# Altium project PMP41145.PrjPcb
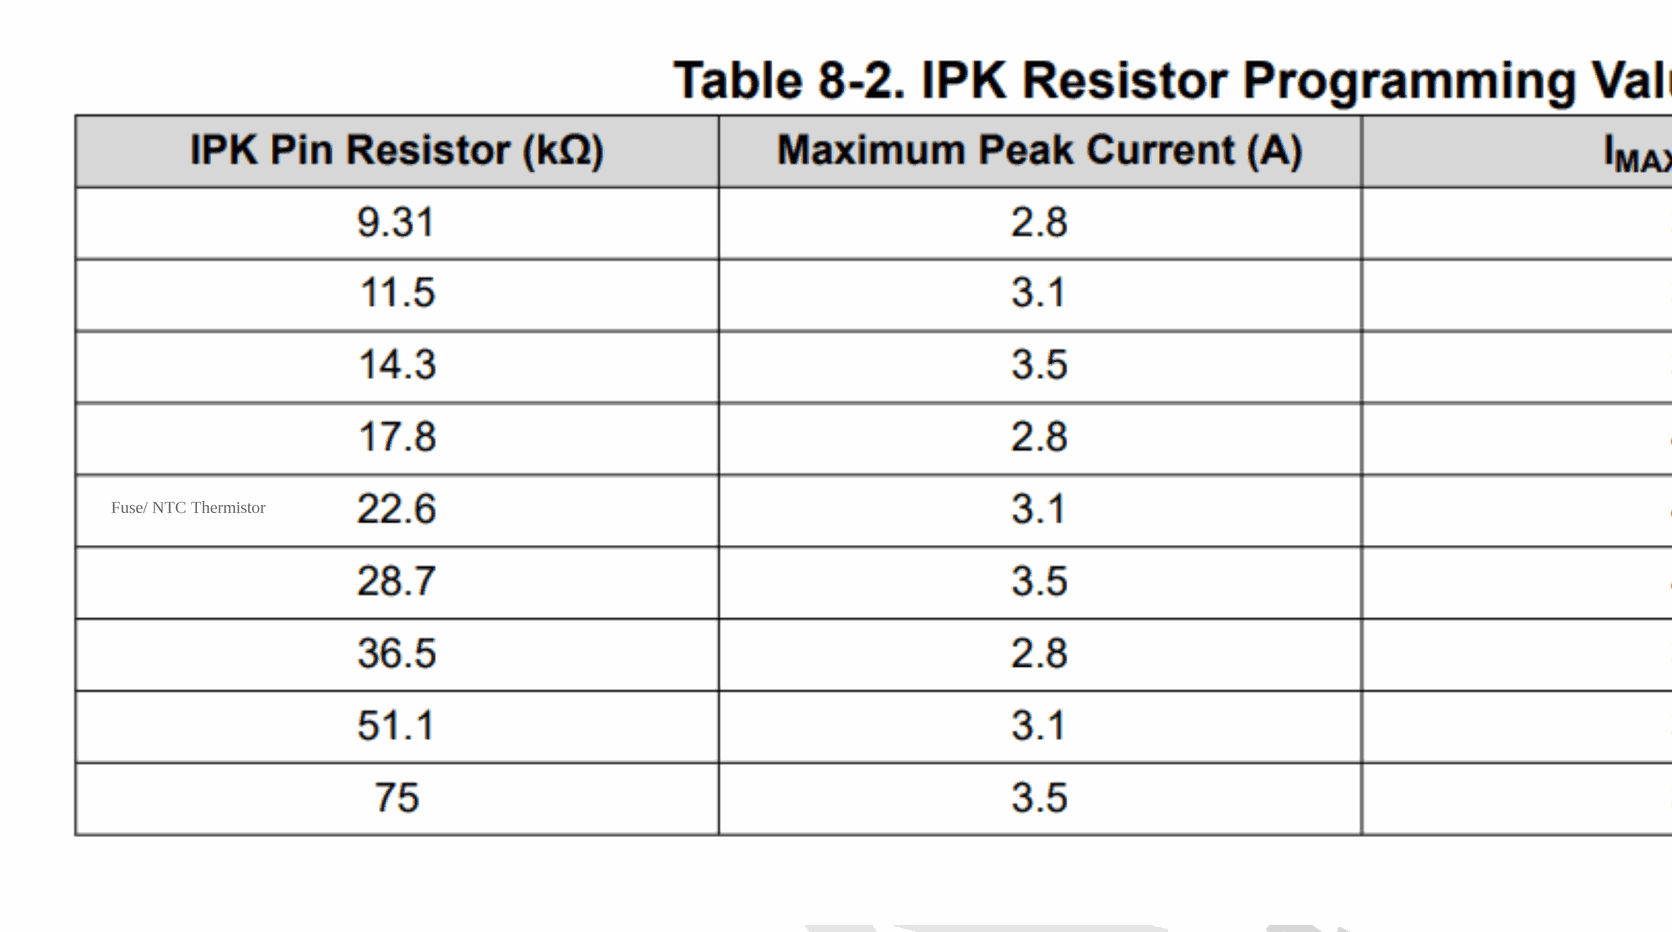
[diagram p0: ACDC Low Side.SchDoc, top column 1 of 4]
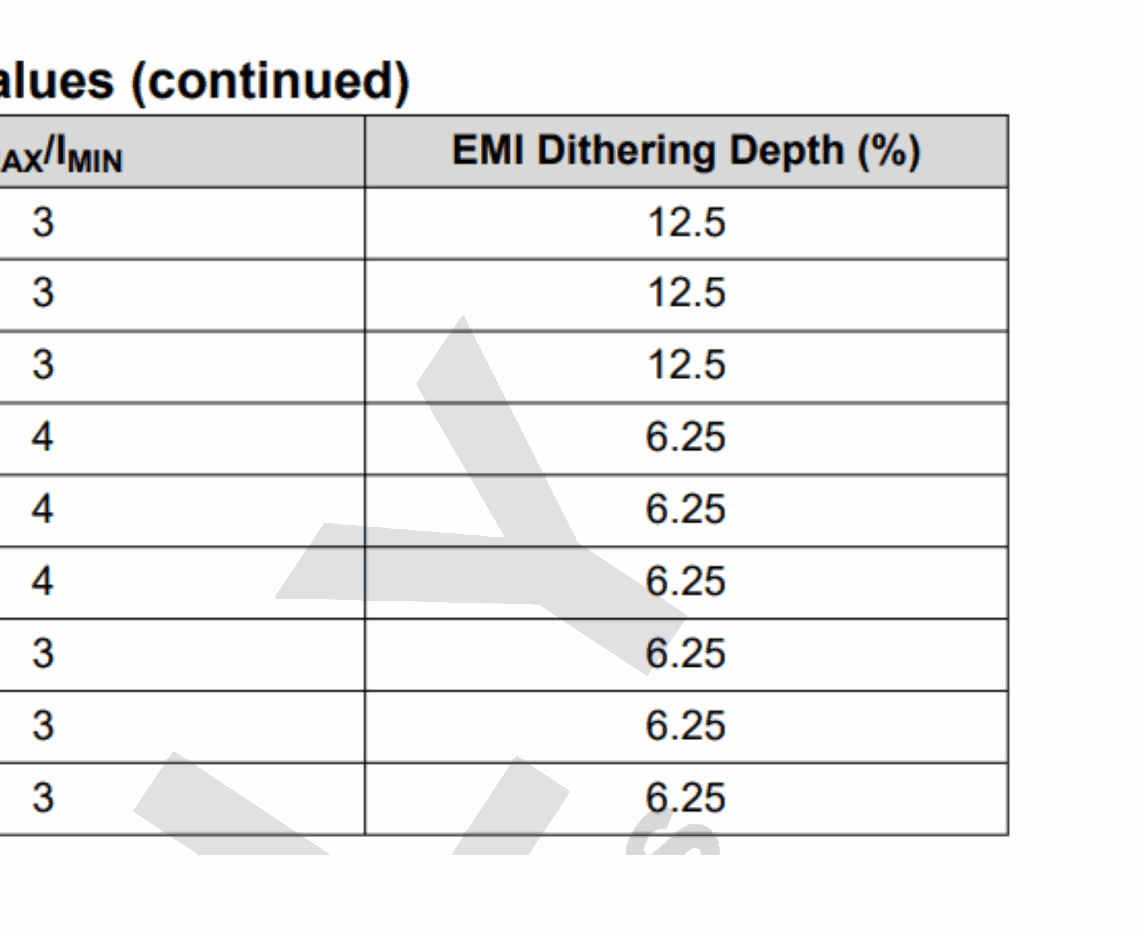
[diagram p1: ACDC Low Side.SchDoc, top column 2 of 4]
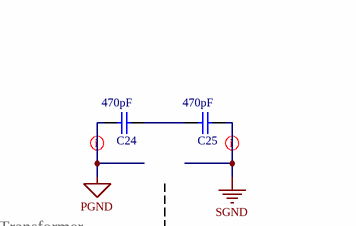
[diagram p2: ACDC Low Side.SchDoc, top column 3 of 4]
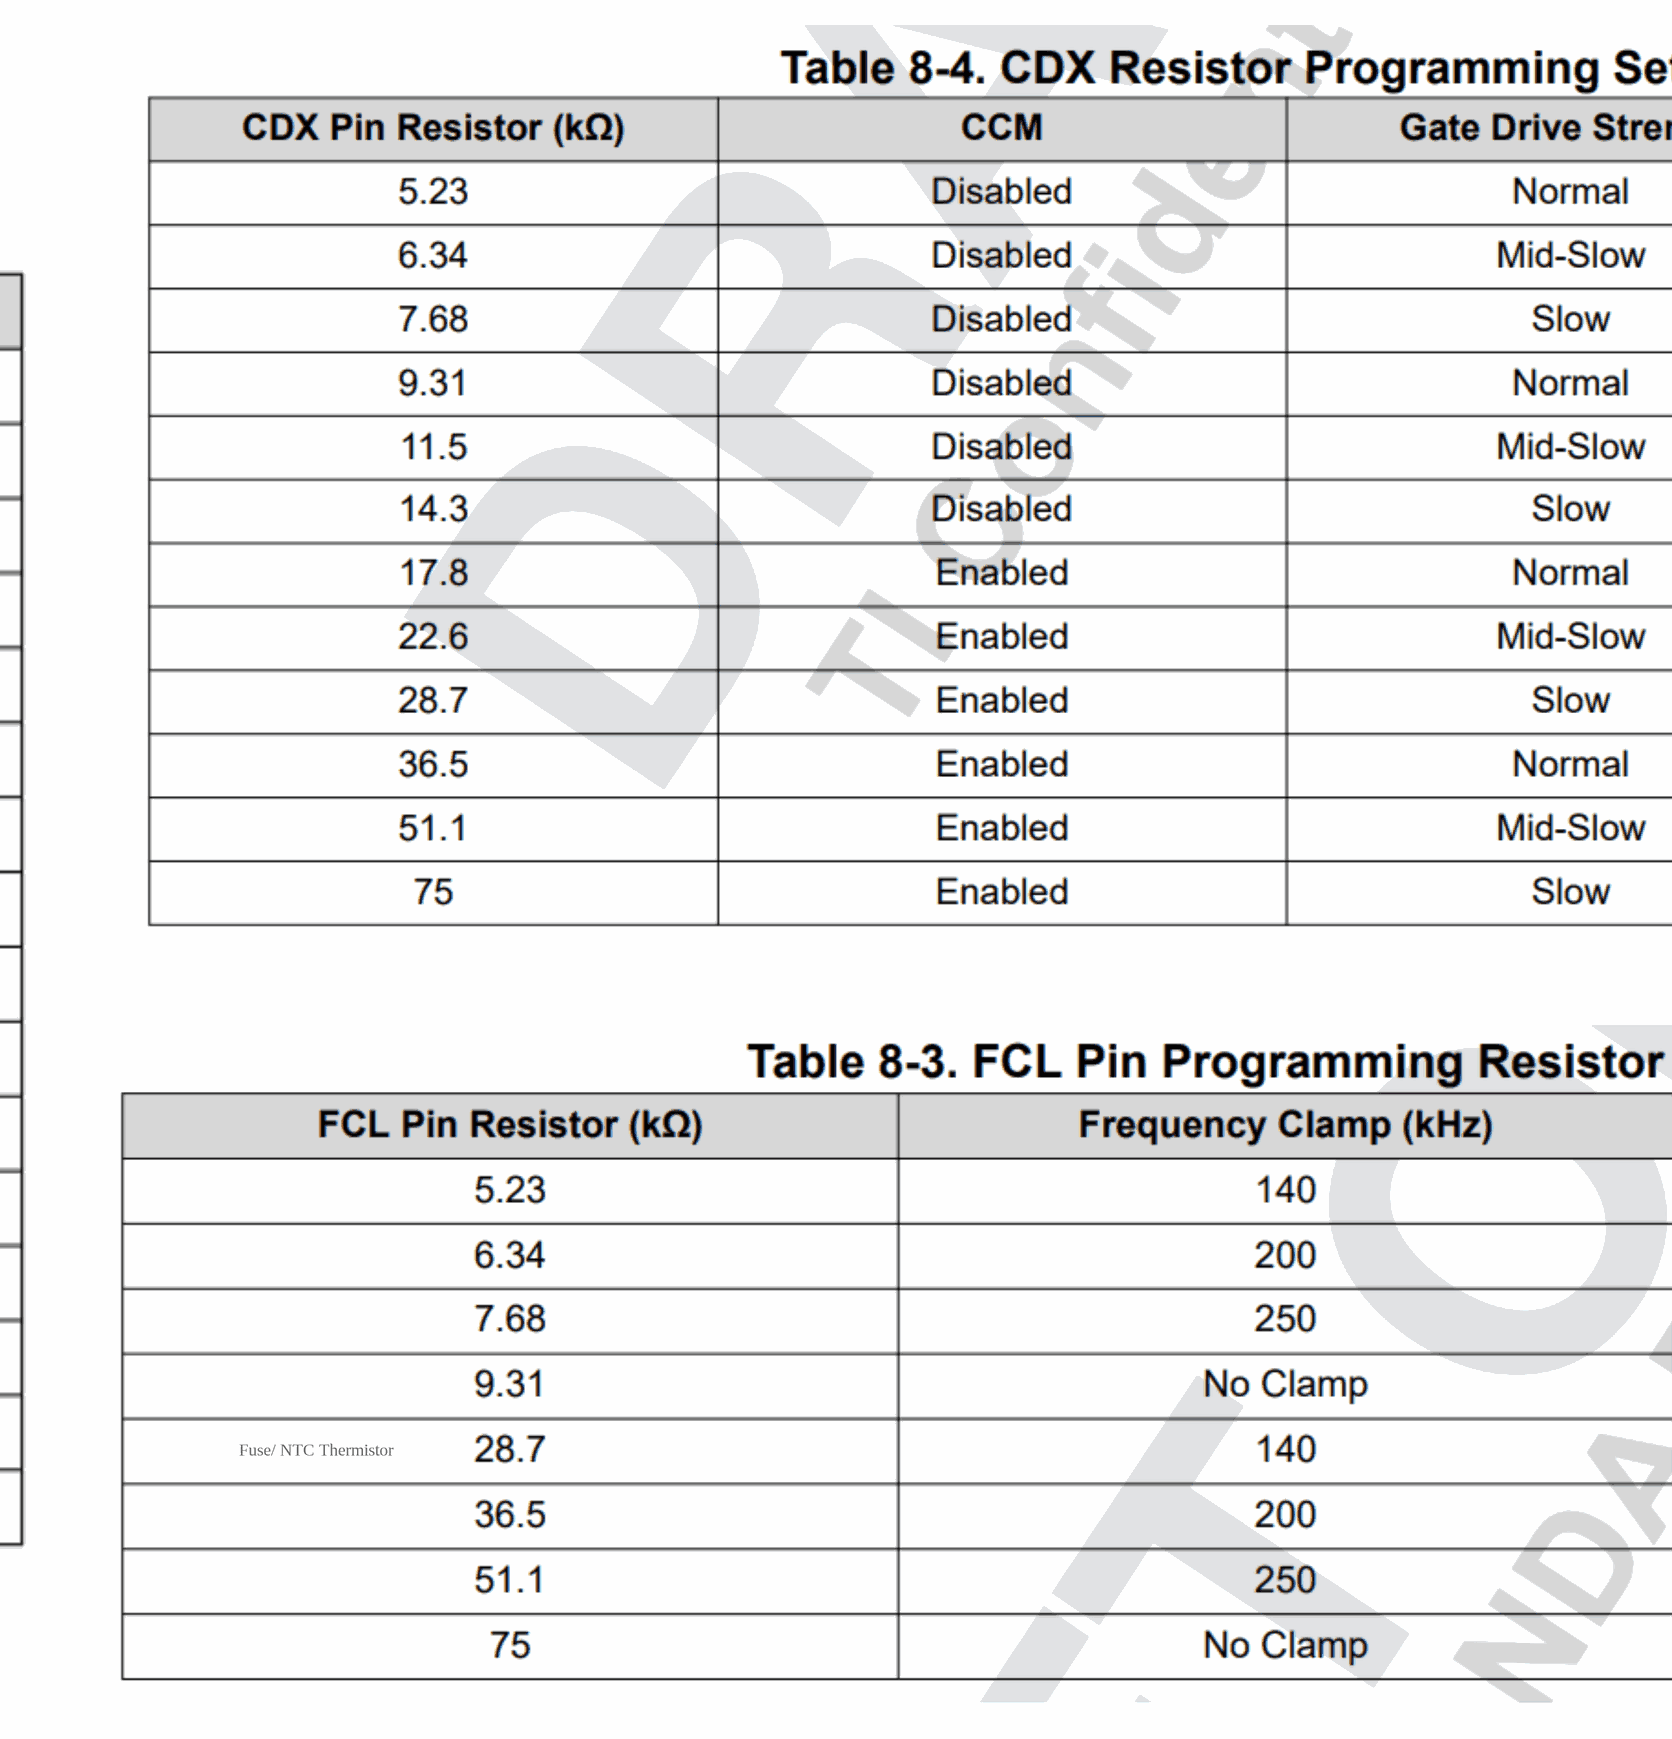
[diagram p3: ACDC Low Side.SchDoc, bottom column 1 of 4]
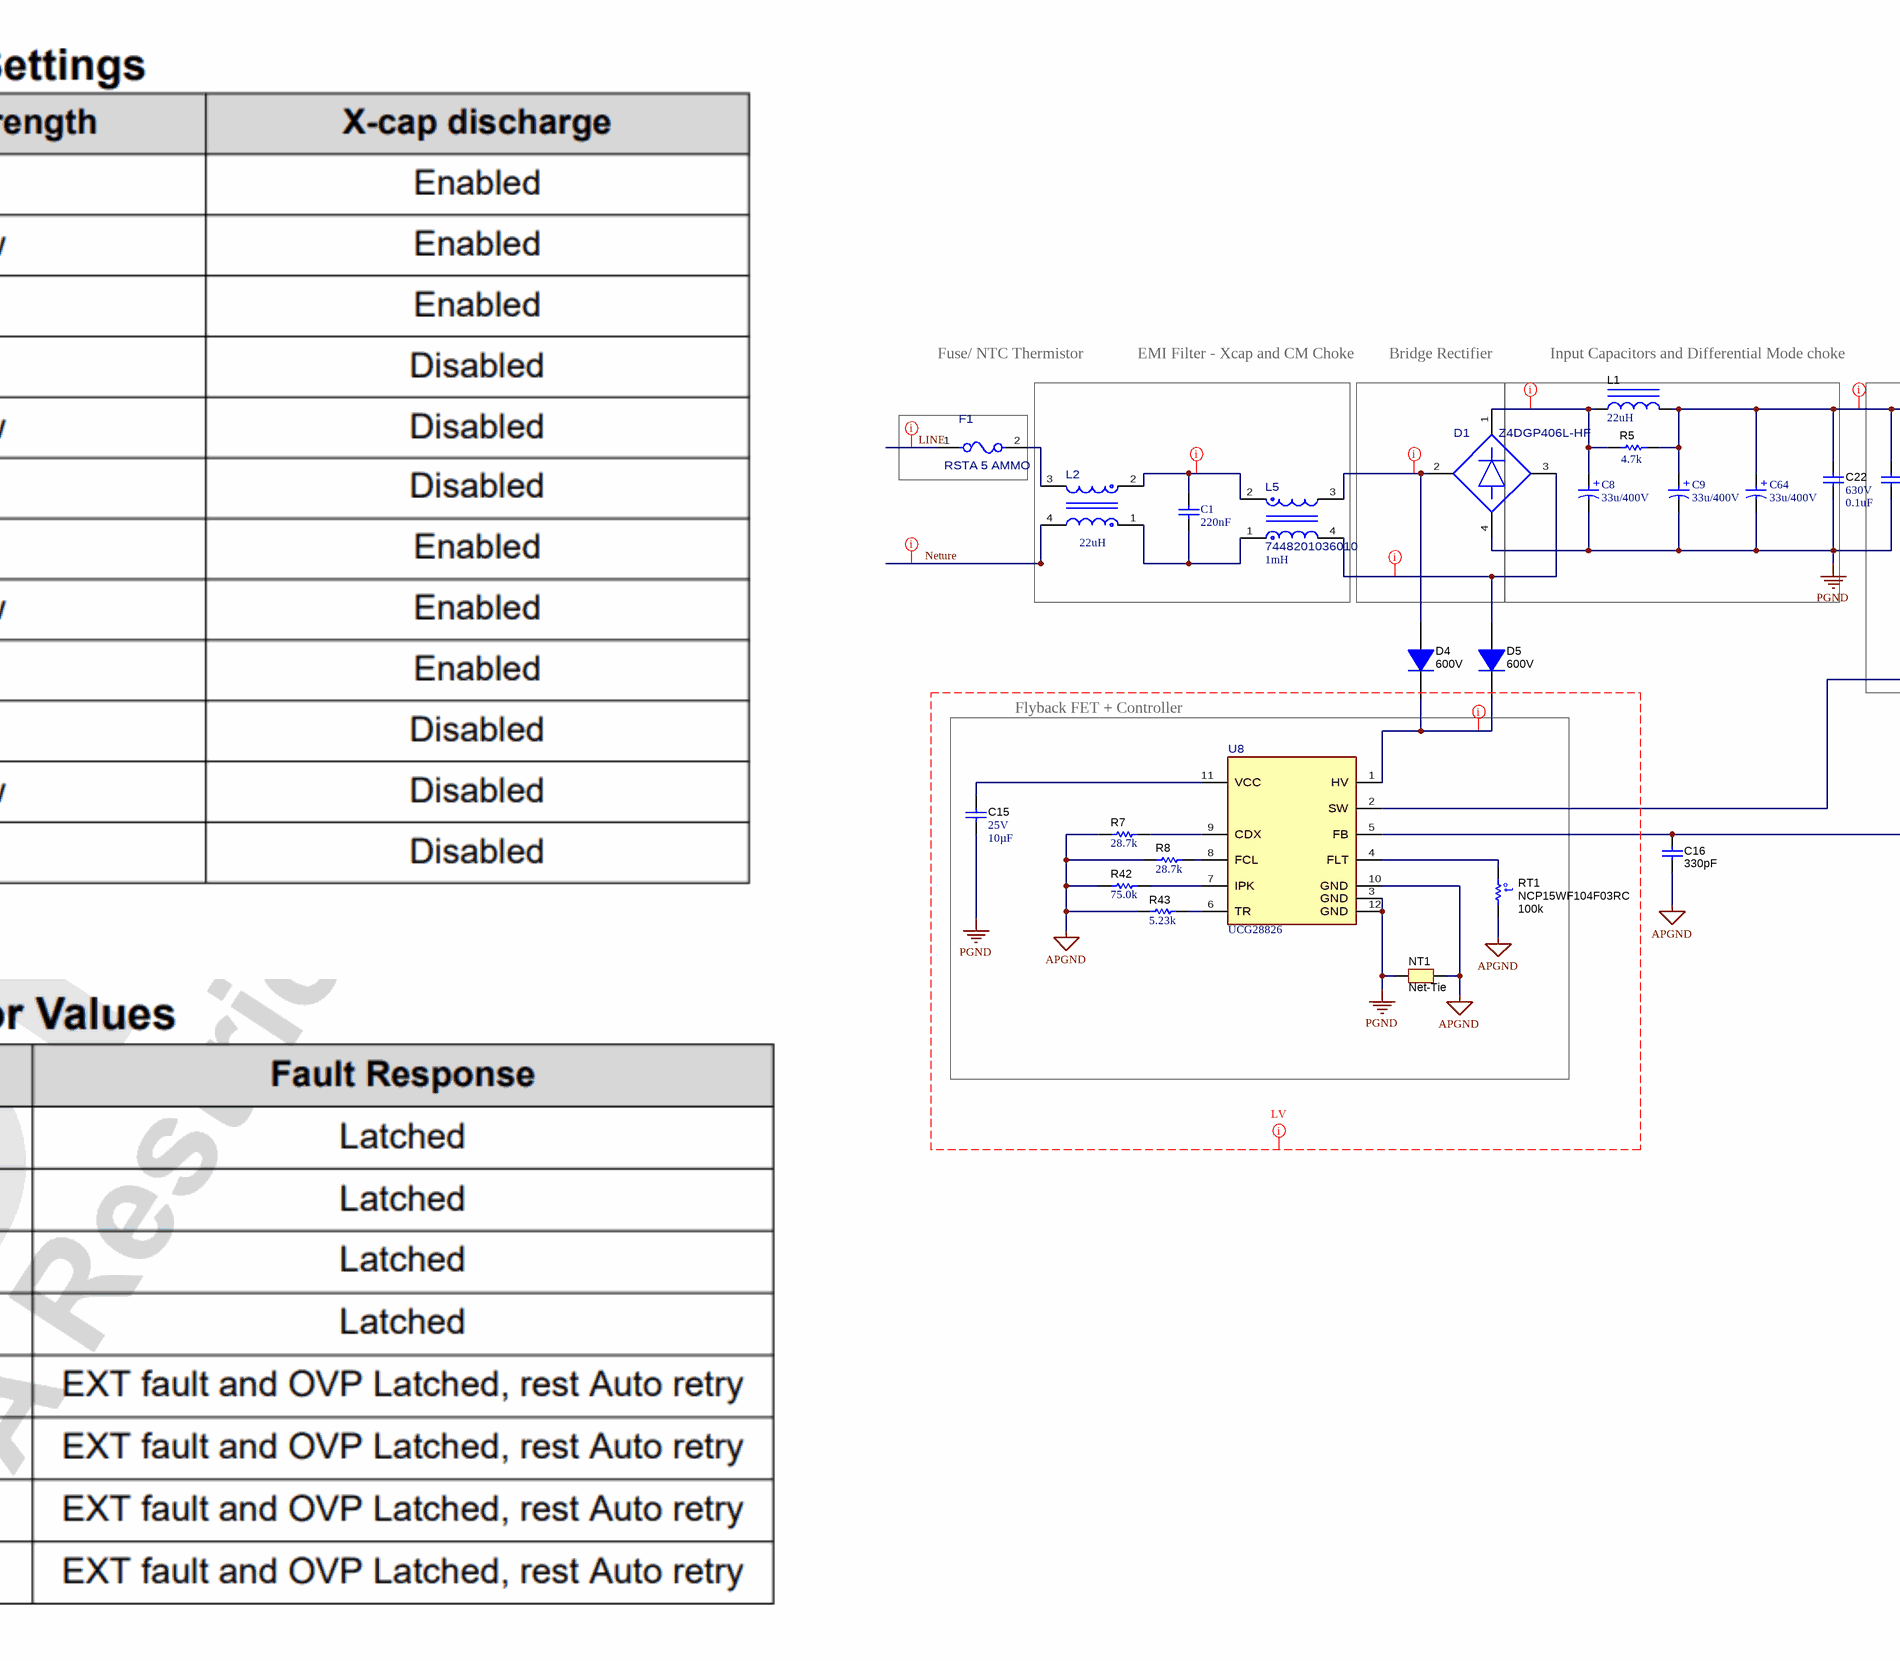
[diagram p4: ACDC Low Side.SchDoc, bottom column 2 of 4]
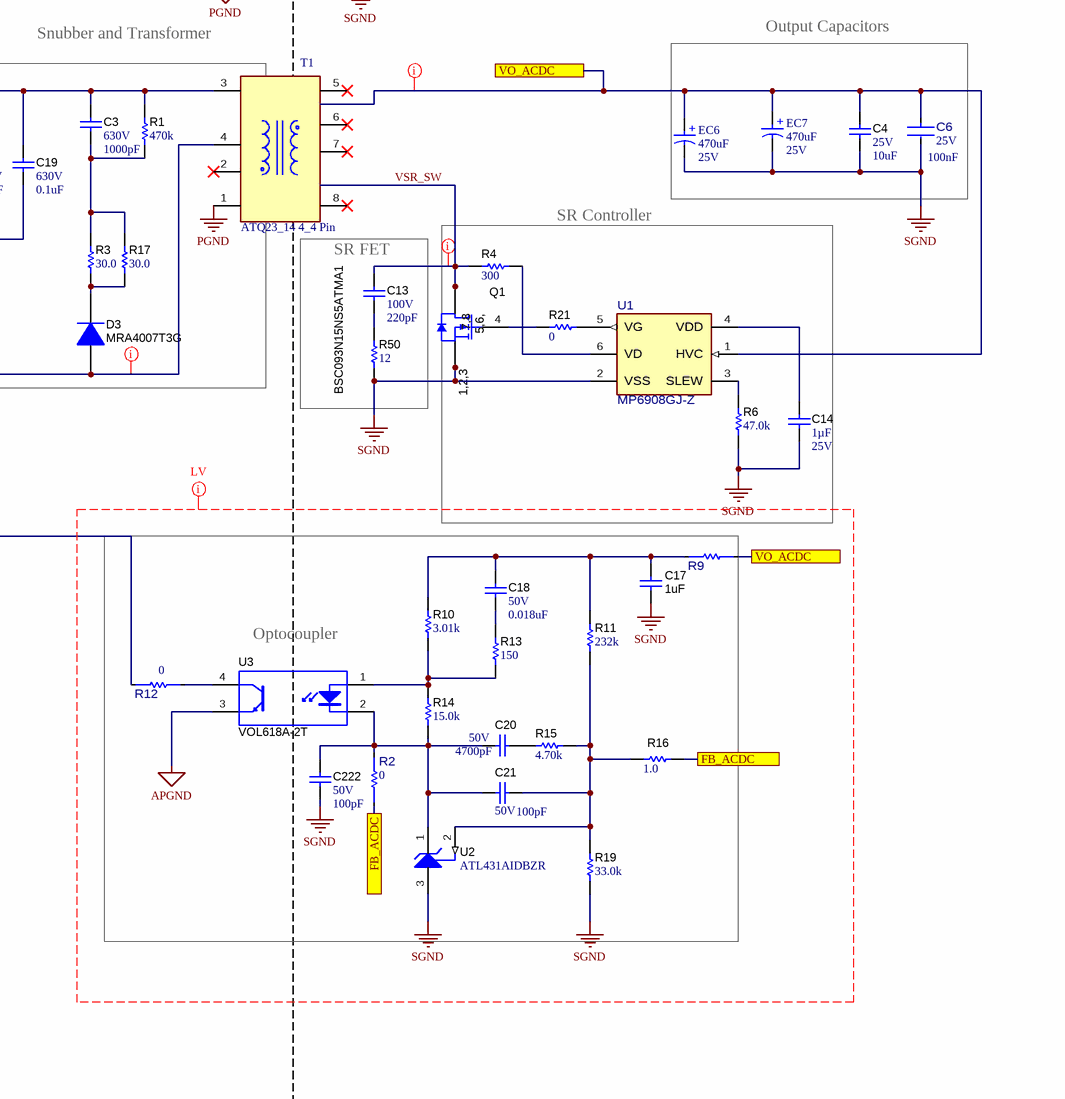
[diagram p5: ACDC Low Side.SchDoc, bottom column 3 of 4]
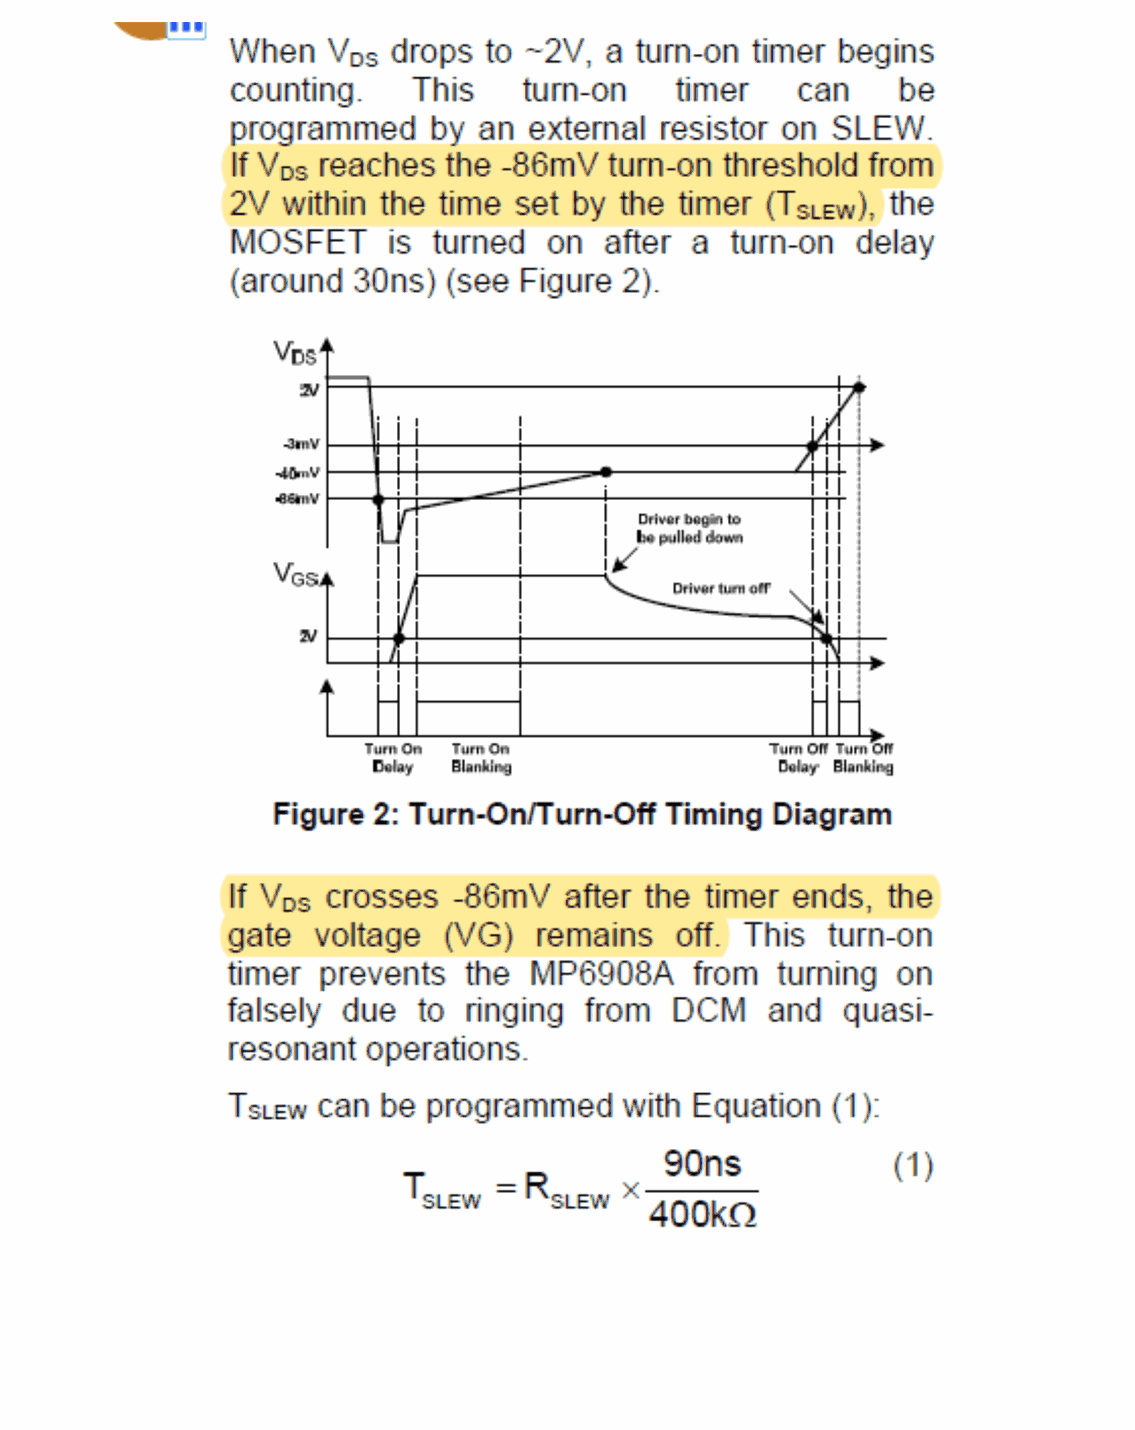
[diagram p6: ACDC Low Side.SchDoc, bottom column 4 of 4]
CopyrightYear: 2018; PCB_Layout: Max Wang; PCB_Rev: E1; PRJ_Customer: Public Release; PRJ_Engineer: Max Wang; PRJ_Number: PMP411145; PRJ_Title: Change in menu Project|Project Options|Parameters; SCH_Rev: E1; TechSupport: http://www.ti.com/support; TID: N/A
1 sheet, 60 parts. Net scope: flat (ports and power ports of the same name join across sheets).
Board file: PMP41145 ACDC.PcbDoc

## Sheet ACDC Low Side.SchDoc
size 431 x 279 mm; Date: Not shown in title block; ApprovedBy: Not shown in title block; CheckedBy: Not shown in title block; Author: Not shown in title block; CompanyName: Not shown in title block; Engineer: Not shown in title block; Organization: Not shown in title block; Address1: Not shown in title block; Address2: Not shown in title block; Address3: Not shown in title block; Address4: Not shown in title block; DocumentNumber: 1; Revision: Use project parameter SCH_Rev; SheetNumber: 1; SheetTotal: 1; PageSetup: Record=PageOptions¦CenterHorizontal=True¦CenterVertical=True¦PrintScale=1.00¦XCorrection=1.00¦YCorrection=1.00¦PrintKind=0¦BorderSize=5000000¦LeftOffset=0¦BottomOffset=0¦Orientation=2¦PaperLength=1000¦PaperWidth=1000¦Scale=100¦PaperSource=15¦PrintQuality=600¦MediaType=1¦DitherType=10¦PaperKind=Letter¦PrintScaleMode=1

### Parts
C1  value 220nF  [X CAP small form 7_10_8]  (hidden comment: 890324023028)
C3  VDC_V: 630V  ValueDisplayed: 1000pF  [1206]  (hidden comment: GRM31BR72J102KW01L)
C4  VDC_V: 25V  ValueDisplayed: 10uF  [0805_HV]  (hidden comment: TMK212BBJ106KG-T)
C6  VDC_V: 25V  Cap_F: 100nF  [FP-CGA3E2X8R1E104K080AD_0603-MFG]  (hidden comment: CGA3E2X8R1E104K080AD)
C8  33u/400V  [WCAP-ATG5_D8H16]
C9  33u/400V  [WCAP-ATG5_D8H16]
C13  VDC_V: 100V  ValueDisplayed: 220pF  [0603]  (hidden comment: GRM1885C2A221JA01D)
C14  Cap_F: 1µF  VDC_V: 25V  [0603S]  (hidden comment: CGA3E1X7R1E105K080AC)
C15  VDC_V: 25V  ValueDisplayed: 10µF  [0603]  (hidden comment: GRM188R61E106KA73D)
C16  ValueDisplayed: 330pF  [0402S]  (hidden comment: GRM155R71H331KA01D)
C17  ValueDisplayed: 1uF  [0603S]  (hidden comment: C1608X7R1E105K080AB)
C18  VDC_V: 50V  ValueDisplayed: 0.018uF  [0402]  (hidden comment: GRM155R71H183KA12D)
C19  VDC_V: 630V  ValueDisplayed: 0.1uF  [1206_180]  (hidden comment: C3216X7T2W104M160AA)
C20  VDC_V: 50V  ValueDisplayed: 4700pF  [0402]  (hidden comment: GRM155R71H472KA01D)
C21  VDC_V: 50V  ValueDisplayed: 100pF  [0402S]  (hidden comment: 885012205055)
C22  VDC_V: 630V  ValueDisplayed: 0.1uF  [1206_180]  (hidden comment: C3216X7T2W104M160AA)
C24  Cap_F: 470pF  [WCAP-CSSA_1808_L4.5W2H1.6]  (hidden comment: 885362210009)
C25  Cap_F: 470pF  [WCAP-CSSA_1808_L4.5W2H1.6]  (hidden comment: 885362210009)
C64  33u/400V  [WCAP-ATG5_D8H16]
C222  VDC_V: 50V  ValueDisplayed: 100pF  [0402S]  (hidden comment: 885012205055)
D1  Z4DGP406L-HF  [FP-Z4DGP406L-HF_SMT_8MM1_10MM5-MFG]
D3  MRA4007T3G  [SMA]
D4  value 600V  [SOD-123]  (hidden comment: ES1JFL)
D5  value 600V  [SOD-123]  (hidden comment: ES1JFL)
EC6  value 470uF  Voltage: 25V  [CE05.5P254L11]  (hidden comment: ECAP_LAYDOWN)
EC7  value 470uF  Voltage: 25V  [CE05.5P254L11]  (hidden comment: ECAP_LAYDOWN)
F1  RSTA 5 AMMO  [FUSE]
L1  ValueDisplayed: 22uH  [WE-TI_5075]  (hidden comment: 7447462220)
L2  value 22uH  [L-T8*5]  (hidden comment: CMP-0088773-1)
L5  7448201036010  value 1mH  [CM Choke_Small]
NT1  Net-Tie  [Net-Tie_10milWide_30milLong]  (net tie, no BOM)
Q1  BSC093N15NS5ATMA1  [PG-TDSON-8]
R1  ValueDisplayed: 470k  [0805_HV]  (hidden comment: CRCW0805470KJNEA)
R2  Res_ohm: 0  [FP-CRCW04020000Z0EDHP_0402-MFG]  (hidden comment: CRCW04020000Z0EDHP)
R3  ValueDisplayed: 30.0  [1206]  (hidden comment: RC1206FR-0730RL)
R4  ValueDisplayed: 300  [0603]  (hidden comment: RC0603FR-07300RL)
R5  ValueDisplayed: 4.7k  [1206]  (hidden comment: CRCW12064K70JNEA)
R6  ValueDisplayed: 47.0k  [0603]  (hidden comment: CRCW060347K0FKEA)
R7  ValueDisplayed: 28.7k  [0402]  (hidden comment: CRCW040228K7FKED)
R8  ValueDisplayed: 28.7k  [0402]  (hidden comment: CRCW040228K7FKED)
R9  CRCW04020000Z0EDHP  [FP-CRCW04020000Z0EDHP_0402-MFG]  (value not drawn)
R10  ValueDisplayed: 3.01k  [0402]  (hidden comment: CRCW04023K01FKED)
R11  ValueDisplayed: 232k  [0603]  (hidden comment: RC0603FR-07232KL)
R12  Res_ohm: 0  [FP-CRCW04020000Z0EDHP_0402-MFG]  (hidden comment: CRCW04020000Z0EDHP)
R13  ValueDisplayed: 150  [0402]  (hidden comment: CRCW0402150RFKED)
R14  ValueDisplayed: 15.0k  [0402]  (hidden comment: CRCW040215K0FKED)
R15  ValueDisplayed: 4.70k  [0402]  (hidden comment: RC0402FR-074K7L)
R16  ValueDisplayed: 1.0  [0402]  (hidden comment: CRCW04021R00JNED)
R17  ValueDisplayed: 30.0  [1206]  (hidden comment: RC1206FR-0730RL)
R19  ValueDisplayed: 33.0k  [0603]  (hidden comment: CRCW060333K0FKEA)
R21  ValueDisplayed: 0  [0201]  (hidden comment: CRCW02010000Z0ED)
R42  ValueDisplayed: 75.0k  [0402S]  (hidden comment: CRCW040275K0FKED)
R43  ValueDisplayed: 5.23k  [0402]  (hidden comment: CRCW04025K23FKED)
R50  ValueDisplayed: 12  [0603]  (hidden comment: CRCW060312R0JNEA)
RT1  NCP15WF104F03RC  value 100k  [0402S]
T1  ATQ23_14 4_4 Pin  [ATQ23.9_13.8_Remove Flywire]
U1  MP6908GJ-Z  [FP-MP6908GJ-Z_TSOT23-6-MFG]
U2  ATL431AIDBZR  [DBZ0003A_N]
U3  VOL618A-2T  [SOP254P1020X230-4]
U8  UCG28826  [REZ0012A-MFG]

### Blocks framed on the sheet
Output Capacitors: C4 C6 EC6 EC7
SR Controller: C14 Q1 R4 R6 R21 U1
SR FET: C13 R50
Flyback FET + Controller: C15 NT1 R7 R8 R42 R43 RT1 U8
Optocoupler: C17 C18 C20 C21 C222 R2 R9-R16 R19 U2 U3

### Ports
FB_ACDC, VO_ACDC

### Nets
APGND: C16.2 NT1.2 R7.1 R8.1 R42.1 R43.1 RT1.1 U3.3(E) U8.10(GND)
PGND: C8.2(N) C9.2(N) C15.2 C19.2 C22.2 C24.1 C64.2(N) D1.4(-) NT1.1 T1.1 U8.3(GND) U8.12(GND)
SGND: C4.2 C6.2 C14.2 C17.1 C25.2 C222.1 EC6.2(N) EC7.2(N) Q1.1(S) Q1.2(S) Q1.3(S) R6.1 R19.1 R50.1 U1.2(VSS) U2.3(ANODE)
FB_ACDC: R2.1 R16.2 ; port FB_ACDC
LINE: F1.1
Neture: L2.4
VO_ACDC: C4.1 C6.1 EC6.1(P) EC7.1(P) R9.2 U1.1(HVC) ; port VO_ACDC
VSR_SW: C13.1 Q1.5(D) Q1.6(D) Q1.7(D) Q1.8(D) Q1.9(D) R4.1
NetC1_1: C1.1 L2.1 L5.1
NetC1_2: C1.2 L2.2 L5.2
NetC3_1: C3.1 R1.1 R3.2 R17.2
NetC3_2: C3.2 C9.1(P) C19.1 C22.1 C64.1(P) L1.2 R1.2 R5.2 T1.3
NetC8_1: C8.1(P) D1.1(+) L1.1 R5.1
NetC13_2: C13.2 R50.2
NetC14_1: C14.1 U1.4(VDD)
NetC15_1: C15.1 U8.11(VCC)
NetC16_1: C16.1 R12.1 U8.5(FB)
NetC17_2: C17.2 C18.1 R9.1 R10.2 R11.2
NetC18_2: C18.2 R13.2
NetC20_1: C20.1 R15.1
NetC20_2: C20.2 C21.2 C222.2 R2.2 R14.1 U2.1(CATHODE) U3.2(K)
NetC21_1: C21.1 R11.1 R15.2 R16.1 R19.2 U2.2(REF)
NetC24_2: C24.2 C25.1
NetD1_2: D1.2(1_~) D4.2(A) L5.3
NetD1_3: D1.3(2_~) D5.2(A) L5.4
NetD3_1: D3.1(K) R3.1 R17.1
NetD3_2: D3.2(A) T1.4 U8.2(SW)
NetD4_1: D4.1(K) D5.1(K) U8.1(HV)
NetF1_2: F1.2 L2.3
NetQ1_4: Q1.4(G) R21.1
NetR4_2: R4.2 U1.6(VD)
NetR6_2: R6.2 U1.3(SLEW)
NetR7_2: R7.2 U8.9(CDX)
NetR8_2: R8.2 U8.8(FCL)
NetR10_1: R10.1 R13.1 R14.2 U3.1(A)
NetR12_2: R12.2 U3.4(C)
NetR21_2: R21.2 U1.5(VG)
NetR42_2: R42.2 U8.7(IPK)
NetR43_2: R43.2 U8.6(TR)
NetRT1_2: RT1.2 U8.4(FLT)

Not connected (* = marked no-connect by the designer): T1 2* 5* 6* 7* 8*

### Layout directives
net class VAC: LINE, NetC1_2, NetD1_2, NetD1_3, Neture
net class High Voltage: NetC3_2, NetC8_1, NetD4_1
net class Switch Node: NetD3_2
net class PGND: PGND
net class SGND: SGND, VO_ACDC, VSR_SW
net class Low Voltage: APGND, PGND, SGND

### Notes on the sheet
- Fuse/ NTC Thermistor
- EMI Filter - Xcap and CM Choke
- Bridge Rectifier
- (near L1) Input Capacitors and Differential Mode choke
- Snubber and Transformer

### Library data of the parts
C1 = CMP-0112463-1: X2 Film Capacitor, THT, L10 x W6 x H12mm, 220nF, 275V; Manufacturer: DongGuan Chengxi; PartNumber: X2 0.22uF/224K/275V; Capacitance Tolerance: +/-10%; Dissipation Factor @100kHz: 2%; Dissipation Factor @10kHz: 0.2%; Dissipation Factor @1kHz: 0.1%; Insulation Resistance: 30000MOhm; Match Code: WCAP-FTX2; Pitch: 10mm; Rate of Voltage Rise: 300V/us; Technical Reference: MX2P010224K275ASPB16000
C3 = CMP-0008909-2: CAP, CERM, 1000 pF, 630 V, +/- 10%, X7R, 1206; Manufacturer: MuRata; TaMin_C: -55°C; Polarized: N; SizeAreaWB_mm2: 10.92; Value1: Unknown; U/M: EA; Value: 1000pF; TaMax_C: 125°C; SizeZ_mm: 1.35; SizeX_mm: 3.2; SizeY_mm: 1.6; SizeArea_mm2: 5.12; Cap_F: 1nF; AEC Category: Q200
C4 = CMP-0008414-2: CAP, CERM, 10 uF, 25 V, +/- 10%, X5R, 0805; Manufacturer: Taiyo Yuden; TaMin_C: -55°C; Polarized: N; SizeAreaWB_mm2: 6.75; Value1: Unknown; U/M: EA; Value: 10uF; TaMax_C: 85°C; SizeZ_mm: 1.45; SizeX_mm: 2; SizeY_mm: 1.25; Cap_Case: 0805; SizeArea_mm2: 2.5; Cap_F: 10µF; AEC Category: Q200
C6 = CMP-0086497-1: 0.1µF ±10% 25V Ceramic Capacitor X8R 0603 (1608 Metric); Manufacturer: TDK Corporation; SizeZ_mm: 0.95mm; TempCo: 15%; AEC Grade: Grade 0; AEC Qualified: Yes; Symbol Name: SYM-CGA3E2X8R1E104K080AD; Value: 100nF
C8 C9 C64 = CMP-0116785-1: Aluminum Electrolytic Capacitor, Radial, THT, D8 x H20mm, 33µF, 400V; Manufacturer: Yongming; Manufacturer Part Number: 860021374027; PartNumber: KCMD2002G330MF; Capacitance Tolerance: +0%/-40%; Dissipation Factor: 15%; Endurance: 2000h; Leakage Current: 264uA; Match Code: WCAP-ATG5; Ripple Current: 200mA; Technical Reference: ATJE1602203400DSPA7B0LR; Value: 33uF
C13 = CMP-0007256-4: CAP, CERM, 220 pF, 100 V, +/- 5%, C0G/NP0, 0603; Manufacturer: MuRata; TaMin_C: -55°C; Polarized: N; SizeAreaWB_mm2: 4.68; Value1: Unknown; U/M: EA; Value: 220pF; TaMax_C: 125°C; SizeZ_mm: 1; SizeX_mm: 1.6; SizeY_mm: 0.8; SizeArea_mm2: 1.28; AEC Category: Q200
C14 = CMP-0076705-1: CAP, CERM, 1 µF, 25 V,+/- 10%, X7R, AEC-Q200 Grade 1, 0603; Manufacturer: TDK; SizeAreaWB_mm2: 4.68; SizeArea_mm2: 1.28; AEC Qualified: Y; AEC Category: Q200; Value: 1uF; TaMax_C: 125°C; SizeZ_mm: 1.0; AEC Grade: 1; Polarized: N; TaMin_C: -55°C; SizeY_mm: 0.8; U/M: EA; SizeX_mm: 1.6; Cap_Case: 1.6x0.8x0.8mm
C15 = CMP-0860569-1: CAP, CERM, 10 µF, 25 V,+/- 10%, X5R, 0603; Manufacturer: MuRata; SizeZ_mm: 1; AEC Category: Q200; AEC Qualified: N; TaMin_C: -55°C; SizeY_mm: 0.8; SizeAreaWB_mm2: 4.68; SizeArea_mm2: 1.28; TaMax_C: 85°C; SizeX_mm: 1.6; Value: 10uF; U/M: EA
C16 = CMP-0006687-2: CAP, CERM, 330 pF, 50 V, +/- 10%, X7R, 0402; Manufacturer: MuRata; TaMin_C: -55°C; Polarized: N; SizeAreaWB_mm2: 3; Value1: Unknown; U/M: EA; Value: 330pF; TaMax_C: 125°C; SizeZ_mm: 0.6; SizeX_mm: 1; SizeY_mm: 0.5; Cap_Case: 0402; Value2: 50V; AEC Category: Q200
C17 = CMP-0007040-4: CAP, CERM, 1 µF, 25 V, +/- 10%, X7R, 0603; Manufacturer: TDK; Polarized: N; CompType: Capacitor; Value: 1uF; U/M: EA; Cap_F: 1µF; Value1: Unknown; VDC_V: 25V; TaMin_C: -55°C; TaMax_C: 125°C; Cap_Case: 0603; AEC Category: Q200; SizeArea_mm2: 1.28; SizeAreaWB_mm2: 4.68; SizeX_mm: 1.6; SizeY_mm: 0.8; SizeZ_mm: 1
C18 = CMP-0006681-2: CAP, CERM, 0.018 uF, 50 V, +/- 10%, X7R, 0402; Manufacturer: MuRata; TaMin_C: -55°C; Polarized: N; SizeAreaWB_mm2: 3; Value1: Unknown; U/M: EA; TaMax_C: 125°C; SizeZ_mm: 0.6; SizeX_mm: 1; SizeY_mm: 0.5; Cap_F: 18nF; AEC Category: Q200
C19 C22 = CMP-0008729-1: CAP, CERM, 0.1 uF, 450 V, +/- 20%, X7T, 1206; Manufacturer: TDK; TaMin_C: -55°C; Polarized: N; SizeAreaWB_mm2: 10.92; Value1: Unknown; U/M: EA; Value: 0.1uF; TaMax_C: 125°C; SizeZ_mm: 1.8; SizeX_mm: 3.2; SizeY_mm: 1.6; Cap_Case: 1206; Value2: 450V; SizeArea_mm2: 5.12; Cap_F: 100nF; AEC Category: Q200
C20 = CMP-0006692-2: CAP, CERM, 4700 pF, 50 V, +/- 10%, X7R, 0402; Manufacturer: MuRata; TaMin_C: -55°C; Polarized: N; SizeAreaWB_mm2: 3; Value1: Unknown; U/M: EA; Value: 4700pF; TaMax_C: 125°C; SizeZ_mm: 0.6; SizeX_mm: 1; SizeY_mm: 0.5; Cap_F: 4.7nF; AEC Category: Q200
C21 C222 = CMP-0006230-2: CAP, CERM, 100 pF, 50 V, +/- 10%, X7R, 0402; Manufacturer: Wurth Elektronik; TaMin_C: -55°C; Polarized: N; SizeAreaWB_mm2: 3; Value1: Unknown; U/M: EA; Value: 100pF; TaMax_C: 125°C; SizeZ_mm: 0.6; SizeX_mm: 1; SizeY_mm: 0.5; Cap_Case: 0402; AEC Category: Q200
C24 C25 = CMP-0115938-1: WCAP-CSSA Multilayer Ceramic Chip Safety Capacitor, size 1808, X7R Class II, 470pF, 250VAC; Manufacturer: Wurth Elektronik; Capacitance Tolerance: +/-10%; Case/Size Code: 1808; Dissipation Factor: 2.5%; Impulse Voltage: 2500VDC; Insulation Resistance: 10GOhm; Rated Voltage (AC): 250V; Safety Class: X2; Technical Reference: X7R1808471KB50IFCT10000
D1 = CMP-0120719-1: Bridge Rectifier Single Phase Standard 600 V Surface Mount Z4-D; Manufacturer: Comchip; AEC Qualified: No; SizeZ_mm: 1.45mm; TJmax_C: 175°C; Vf_V: 600V; Cap_F: 45pF; Forward Current: 4A; Max Surge Forward Current: 150A; Peak Reverse Current: 0.08uA
D3 = CMP-0077082-2: Diode, Standard Recovery Rectifier, 1000 V, 1 A, AEC-Q101, SMA; Manufacturer: ON Semiconductor; Value2: 1.1V; TJmax_C: 175°C; SizeX_mm: 5.59; Green_Lifecycle: Active; Value1: 1A; Green_REACh: Passed; AEC Qualified: Y; AEC Category: Q101; SizeArea_mm2: 16.3228; SizeY_mm: 2.92; SizeAreaWB_mm2: 37.3428; Value: 1000V; RJC_CperW: 16.2; SizeZ_mm: 2.87; Vr_V: 1kV
D4 D5 = CMP-0029032-2: Diode, Switching, 600 V, 1 A, SOD-123; Manufacturer: ON Semiconductor; SizeY_mm: 1.7; Io_A: 1A; SizeAreaWB_mm2: 13.095; SizeArea_mm2: 6.545; Vf_V: 1V; TJmax_C: 150°C; SizeX_mm: 3.85; SizeZ_mm: 1.35; Green_Lifecycle: Active; Green_REACh: Passed
EC6 EC7 = ECAP_LAYDOWN: 25V/470uF D5.5*11mm; PartNumber: NPXC1001E471MJTM; Manufacturer: Yongming
F1 = CMP-0120910-1: 5 A 250 V AC 63 V DC Fuse Board Mount (Cartridge Style Excluded) Through Hole Radial, Box; Manufacturer: Bel Fuse; Interrupt_AC: 100A; MeltingTyp: 94A2Sec; SizeZ_mm: 8.1mm; VAC_V: 277V; VDC_V: 63V; Fuse Speed: Slow; AEC Grade: Grade 1; AEC Qualified: Yes; Fuse Current: 5A; Fuse Voltage Drop: 0.075V; Res_ohm: 0.009Ω; Standoff Height: 0.5mm
L1 = CMP-0064517-1: Inductor, Unshielded Drum Core, Ferrite, 22 uH, 1.7 A, 0.102 ohm, TH; Manufacturer: Wurth Elektronik; PartNumber: MCD-0608-220K-UL; Manufacturer: mag-aga; Isat: 1.7A @ 10% inductance drop; Irms: 1.8A @ 40C rise; Green_Lifecycle: Active; SizeAreaWB_mm2: 64; DCR_ohm: 0.102; Green_REACh: Passed; Value: 22uH; Imax_A: 1.7A; SizeZ_mm: 8.5; SizeX_mm: 6; SizeArea_mm2: 36; Ind_H: 22µH; AEC Category: Q200
L2 = CMP-0088773-1: 8*5mm CM choke 22uH; Part Number: 7448201036010; Manufacturer: Wurth Electronics; Imax_A: 3.6A; AEC Qualified: No; Tolerance_%: 30%; Test Frequency: 10kHz; DCR_ohm: 36m; SizeZ_mm: 20.2mm
L5 = CMP-0088773-1: Common Mode Power Line Choke; Manufacturer: Wurth Electronics; Imax_A: 3.6A; AEC Qualified: No; Tolerance_%: 30%; Test Frequency: 10kHz; DCR_ohm: 36m; SizeZ_mm: 20.2mm
NT1 = CMP-0078142-6: Single point connection between nets.
Q1 = CMP-0001046-2: MOSFET, N-CH, 150 V, 87 A, PG-TDSON-8; Alternate Manufacturer: None; Manufacturer: Infineon Technologies; SizeZ_mm: 1.12; ChType: N; Value2: 33 nC; VdsMax_V: 150V; SizeX_mm: 5.99; SizeY_mm: 4.9; Vgs_V: 20V; QgTyp_nC: 33; Value: 150V; SizeArea_mm2: 29.351; AEC Category: Q101; IdsMax_A: 87A; SizeAreaWB_mm2: 55.131; U/M: EA
R1 = CMP-0020554-3: RES, 470 k, 5%, 0.125 W, AEC-Q200 Grade 0, 0805; Manufacturer: Vishay-Dale; Power_W: 125mW; TempCo: 200 ppm/C; Value: 470k; EIA_Code: E24; SizeX_mm: 2; SizeY_mm: 1.25; SizeZ_mm: 1.45; Value2: 0.125W; SizeArea_mm2: 2.5; AEC Qualified: Y; VDC_V: 150V; AEC Category: Q200; AEC Grade: 0
R2 R12 = CMP-0001606-1: RES Thick Film, 0Ω, 0.2W, 0402; Manufacturer: Vishay Dale; AEC Grade: Grade 0; AEC Qualified: Yes; Power_W: 200mW; SizeZ_mm: 0.4mm; VDC_V: 50V; Value: 0
R3 R17 = CMP-0018196-2: RES, 30.0, 1%, 0.25 W, 1206; Manufacturer: Yageo America; Power_W: 250mW; TempCo: 100 ppm/C; Value_Code: 30R0; U/M: EA; Value: 30.0; Res_ohm: 30; SizeX_mm: 3.2; SizeY_mm: 1.6; SizeZ_mm: 1.35; Value2: 0.25W; SizeArea_mm2: 5.12; VDC_V: 200V; AEC Category: Q200
R4 = CMP-0023013-5: RES, 300, 1%, 0.1 W, 0603; Manufacturer: Yageo; Power_W: 100mW; TempCo: 100 ppm/C; Value_Code: 300R; Value: 300; SizeX_mm: 1.6; SizeY_mm: 0.8; SizeZ_mm: 1; Value2: 0.1W; SizeArea_mm2: 1.28; AEC Qualified: N; VDC_V: 75V; AEC Category: Q200; SizeAreaWB_mm2: 4.68
R5 = CMP-0018689-2: RES, 4.7 k, 5%, 0.25 W, 1206; Manufacturer: Vishay-Dale; Power_W: 250mW; TempCo: 200 ppm/C; Value_Code: 4k70; U/M: EA; Value: 4.7k; EIA_Code: E24; SizeX_mm: 3.2; SizeY_mm: 1.6; SizeZ_mm: 1.35; Value2: 0.25W; SizeArea_mm2: 5.12; VDC_V: 200V; AEC Category: Q200
R6 = CMP-0022438-1: RES, 47.0 k, 1%, 0.1 W, AEC-Q200 Grade 0, 0603; Manufacturer: Vishay-Dale; Power_W: 100mW; TempCo: 100 ppm/C; Value_Code: 47k0; U/M: EA; Value: 47.0k; Res_ohm: 47k; SizeX_mm: 1.6; SizeY_mm: 0.8; SizeZ_mm: 1; Value2: 0.1W; SizeArea_mm2: 1.28; AEC Qualified: Y; VDC_V: 75V; AEC Grade: 0; AEC Category: Q200
R7 R8 = CMP-0026220-2: RES, 28.7 k, 1%, 0.063 W, AEC-Q200 Grade 0, 0402; Manufacturer: Vishay-Dale; Power_W: 63mW; TempCo: 100 ppm/C; Value_Code: 28k7; Value: 28.7k; EIA_Code: E96; SizeX_mm: 1; SizeY_mm: 0.5; SizeZ_mm: 0.6; Value2: 0.063W; AEC Qualified: Y; VDC_V: 50V; AEC Category: Q200; AEC Grade: 0
R9 = CMP-0001606-1: RES Thick Film, 0Ω, 0.2W, 0402; Manufacturer: Vishay Dale; AEC Grade: Grade 0; AEC Qualified: Yes; Power_W: 200mW; Res_ohm: 0; SizeZ_mm: 0.4mm; VDC_V: 50V; Value: 0
R10 = CMP-0026329-2: RES, 3.01 k, 1%, 0.063 W, AEC-Q200 Grade 0, 0402; Manufacturer: Vishay-Dale; Power_W: 63mW; TempCo: 100 ppm/C; Value_Code: 3k01; Value: 3.01k; EIA_Code: E96; SizeX_mm: 1; SizeY_mm: 0.5; SizeZ_mm: 0.6; Value2: 0.063W; AEC Qualified: Y; VDC_V: 50V; AEC Category: Q200; AEC Grade: 0
R11 = CMP-0022929-1: RES, 232 k, 1%, 0.1 W, 0603; Manufacturer: Yageo America; Power_W: 100mW; TempCo: 200 ppm/C; U/M: EA; Value: 232k; EIA_Code: E96; SizeX_mm: 1.6; SizeY_mm: 0.8; SizeZ_mm: 1; Value2: 0.1W; SizeArea_mm2: 1.28; VDC_V: 150V; AEC Category: Q200
R13 = CMP-0026022-3: RES, 150, 1%, 0.063 W, AEC-Q200 Grade 0, 0402; Manufacturer: Vishay-Dale; Power_W: 63mW; TempCo: 100 ppm/C; Value_Code: 150R; Value: 150; EIA_Code: E96; SizeX_mm: 1; SizeY_mm: 0.5; SizeZ_mm: 0.6; Value2: 0.063W; AEC Qualified: Y; VDC_V: 50V; AEC Category: Q200; AEC Grade: 0
R14 = CMP-0026027-3: RES, 15.0 k, 1%, 0.063 W, AEC-Q200 Grade 0, 0402; Manufacturer: Vishay-Dale; Power_W: 63mW; TempCo: 100 ppm/C; Value_Code: 15k0; Value: 15.0k; EIA_Code: E96; Res_ohm: 15k; SizeX_mm: 1; SizeY_mm: 0.5; SizeZ_mm: 0.6; Value2: 0.063W; AEC Qualified: Y; VDC_V: 50V; AEC Category: Q200; AEC Grade: 0
R15 = CMP-0026739-1: RES, 4.70 k, 1%, 0.0625 W, 0402; Manufacturer: Yageo America; Power_W: 62.5mW; TempCo: 100 ppm/C; Value_Code: 4k70; U/M: EA; Value: 4.70k; Res_ohm: 4.7k; SizeX_mm: 1; SizeY_mm: 0.5; SizeZ_mm: 0.6; AEC Qualified: N; VDC_V: 50V; AEC Category: Q200
R16 = CMP-0026866-2: RES, 1.0, 5%, 0.063 W, 0402; Manufacturer: Vishay-Dale; Power_W: 63mW; TempCo: 200 ppm/C; Value_Code: 1R00; U/M: EA; Value: 1.0; EIA_Code: E24; Res_ohm: 1; SizeY_mm: 0.5; SizeZ_mm: 0.6; Value2: 0.063W; VDC_V: 50V; AEC Category: Q200
R19 = CMP-0022338-2: RES, 33.0 k, 1%, 0.1 W, 0603; Manufacturer: Vishay-Dale; Power_W: 100mW; TempCo: 100 ppm/C; Value_Code: 33k0; U/M: EA; Value: 33.0k; Res_ohm: 33k; SizeX_mm: 1.6; SizeY_mm: 0.8; SizeZ_mm: 1; Value2: 0.1W; SizeArea_mm2: 1.28; VDC_V: 75V; AEC Category: Q200
R21 = CMP-0027008-4: RES, 0, 5%, 0.05 W, 0201; Manufacturer: Vishay-Dale; Power_W: 50mW; TempCo: ppm/C; Value_Code: 0000; Value: 0; EIA_Code: E24; SizeX_mm: 0.6; SizeY_mm: 0.3; SizeZ_mm: 0.26; Value2: 0.05W; SizeArea_mm2: 0.18; AEC Qualified: N; AEC Category: Q200
R42 = CMP-0026543-1: RES, 75.0 k, 1%, 0.063 W, 0402; Manufacturer: Vishay-Dale; Power_W: 63mW; TempCo: 100 ppm/C; Value_Code: 75k0; U/M: EA; Value: 75.0k; EIA_Code: E96; Res_ohm: 75k; SizeX_mm: 1; SizeY_mm: 0.5; SizeZ_mm: 0.6; Value2: 0.063W; VDC_V: 50V; AEC Category: Q200
R43 = CMP-0026464-2: RES, 5.23 k, 1%, 0.063 W, AEC-Q200 Grade 0, 0402; Manufacturer: Vishay-Dale; Power_W: 63mW; TempCo: 100 ppm/C; Value_Code: 5k23; Value: 5.23k; EIA_Code: E96; SizeX_mm: 1; SizeY_mm: 0.5; SizeZ_mm: 0.6; Value2: 0.063W; AEC Qualified: Y; VDC_V: 50V; AEC Category: Q200; AEC Grade: 0
R50 = CMP-0025712-2: RES, 12, 5%, 0.1 W, 0603; Manufacturer: Vishay-Dale; Power_W: 100mW; TempCo: 200 ppm/C; Value_Code: 12R0; U/M: EA; Value: 12; EIA_Code: E24; SizeX_mm: 1.6; SizeY_mm: 0.8; SizeZ_mm: 1; Value2: 0.1W; SizeArea_mm2: 1.28; VDC_V: 75V; AEC Category: Q200
RT1 = CMP-0002353-2: Thermistor NTC, 100k ohm, 1%, 0402; Manufacturer: MuRata; TaMax_C: 125°C; SizeX_mm: 1; SizeY_mm: 0.5; TaMin_C: -40°C; Power_W: 100mW; SizeZ_mm: 0.6; SizeAreaWB_mm2: 3; U/M: EA
T1 = ATQ23_14 4_4 Pin: PartNumber: ATQ23-14; Manufacturer: Fort Electronics
U1 = CMP-0086802-1: FAST TURN-OFF INTELLIGENT RECTIF; Manufacturer: Monolithic Power Systems; SizeZ_mm: 1mm
U2 = CMP-0066199-1: 2.5V Low Iq Adjustable Precision Shunt Regulator, DBZ0003A (SOT-23-3); Alternate Manufacturer: Texas Instruments; SizeAreaWB_mm2: 14.0; U/M: EA; SizeZ_mm: 1.12; SizeX_mm: 2.5; SizeY_mm: 3.0; SizeArea_mm2: 7.5; CompType: IC
U3 = CMP-0006160-3: Optocoupler, 5 kV, 63-125% CTR, SMT; Manufacturer: Vishay-Semiconductor; CTR (Max): 125%; SizeAreaWB_mm2: 74.42; CTR (Min): 63%; SizeZ_mm: 2.3; SizeX_mm: 10.2; SizeY_mm: 4.1; SizeArea_mm2: 41.82; Voltage_Isolation_Vrms: 5kV
U8 = CMP-0122264-1: Manufacturer: Texas Instruments; SizeZ_mm: 1mm; AEC Qualified: No; AEC Grade: NA; Standoff Height: 0mm

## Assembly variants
001: not fitted C222 R2 R16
